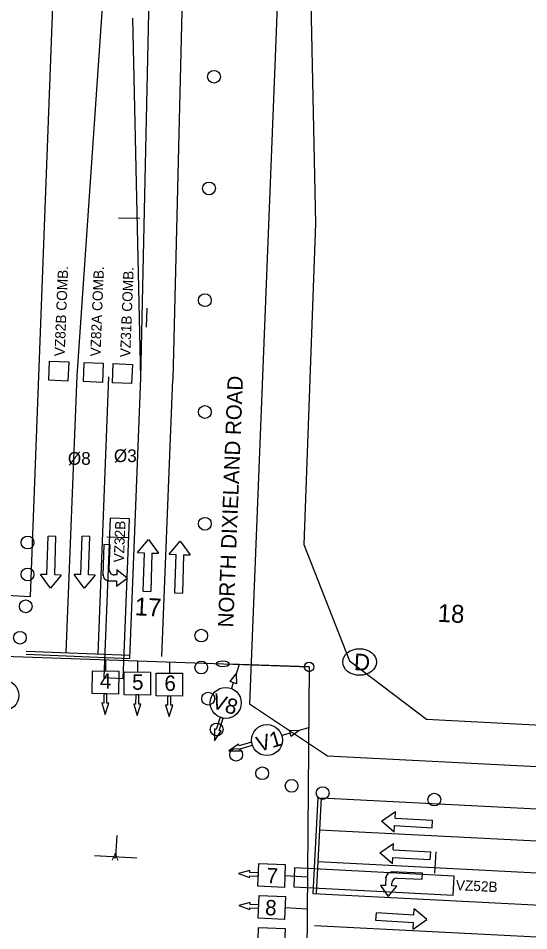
# Model space of a CAD drawing. Extents: x 0 to 1361828, y 0 to 1470398.
# Drawn here: x 680949.1 to 681108.9, y 735115.8 to 735401.5 of the extents above; entities that cross this region are included whole.
import ezdxf

# ---------------------------------------------------------------- set-up
doc = ezdxf.new("R2010")
doc.units = 0
for name, color, linetype in [('$', 7, 'Continuous'), ('090338 Base_Design base 1-1 - R_Horz Alg', 7, 'Continuous'), ('MOT Stage 1', 7, 'Continuous'), ('MOT Stage 1 Lanes', 7, 'Continuous'), ('R_Horz Alg Station', 7, 'Continuous'), ('RW-EX', 7, 'Continuous'), ('RW-PR', 7, 'Continuous'), ('SIGNAL-PLAN VIEW LABLES', 7, 'Continuous'), ('TITEXT', 7, 'Continuous'), ('Video-Zones-pr', 7, 'Continuous')]:
    doc.layers.add(name, color=color, linetype=linetype)

# ---------------------------------------------------------------- blocks, each defined once
blk = doc.blocks.new('BAREL_1503')
at = {"layer": 'MOT Stage 1'}
blk.add_circle((0, 0.01), 2.88, dxfattribs=at)
blk = doc.blocks.new('SARROW_170')
at = {"layer": 'MOT Stage 1'}
for p, q in [((0, 0), (-6, 0)), ((0, -29.42), (0, 0)), ((-6, -29.42), (-6, 0)), ((-6, -29.42), (-11, -29.42)), ((-3, -39.81), (-11, -29.42)), ((5, -29.42), (-3, -39.81)), ((5, -29.42), (0, -29.42))]:
    blk.add_line(p, q, dxfattribs=at)
blk = doc.blocks.new('SARROW_171')
at = {"layer": 'MOT Stage 1'}
for p, q in [((-6, -29.42), (-6, 0)), ((0, 0), (-6, 0)), ((0, -29.42), (0, 0)), ((-6, -29.42), (-11, -29.42)), ((-3, -39.81), (-11, -29.42)), ((5, -29.42), (-3, -39.81)), ((5, -29.42), (0, -29.42))]:
    blk.add_line(p, q, dxfattribs=at)
blk = doc.blocks.new('SARROW_173')
at = {"layer": 'MOT Stage 1'}
for p, q in [((0, 0), (-6, 0)), ((0, -29.42), (0, 0)), ((-6, -29.42), (-6, 0)), ((-6, -29.42), (-11, -29.42)), ((-3, -39.81), (-11, -29.42)), ((5, -29.42), (-3, -39.81)), ((5, -29.42), (0, -29.42))]:
    blk.add_line(p, q, dxfattribs=at)
blk = doc.blocks.new('SARROW_174')
at = {"layer": 'MOT Stage 1'}
for p, q in [((-6, -29.42), (-6, 0)), ((0, 0), (-6, 0)), ((0, -29.42), (0, 0)), ((-6, -29.42), (-11, -29.42)), ((-3, -39.81), (-11, -29.42)), ((5, -29.42), (-3, -39.81)), ((5, -29.42), (0, -29.42))]:
    blk.add_line(p, q, dxfattribs=at)
blk = doc.blocks.new('SARROW_175')
at = {"layer": 'MOT Stage 1'}
for p, q in [((-6, -29.42), (-6, 0)), ((0, 0), (-6, 0)), ((0, -29.42), (0, 0)), ((-6, -29.42), (-11, -29.42)), ((-3, -39.81), (-11, -29.42)), ((5, -29.42), (-3, -39.81)), ((5, -29.42), (0, -29.42))]:
    blk.add_line(p, q, dxfattribs=at)
blk = doc.blocks.new('BAREL_1543')
at = {"layer": 'MOT Stage 1'}
blk.add_circle((0, 0.01), 2.88, dxfattribs=at)
blk = doc.blocks.new('BAREL_1544')
at = {"layer": 'MOT Stage 1'}
blk.add_circle((0, 0.01), 2.88, dxfattribs=at)
blk = doc.blocks.new('BAREL_1545')
at = {"layer": 'MOT Stage 1'}
blk.add_circle((0, 0.01), 2.88, dxfattribs=at)
blk = doc.blocks.new('BAREL_1546')
at = {"layer": 'MOT Stage 1'}
blk.add_circle((0, 0.01), 2.88, dxfattribs=at)
blk = doc.blocks.new('BAREL_1547')
at = {"layer": 'MOT Stage 1'}
blk.add_circle((0, 0.01), 2.88, dxfattribs=at)
blk = doc.blocks.new('BAREL_1548')
at = {"layer": 'MOT Stage 1'}
blk.add_circle((0, 0.01), 2.88, dxfattribs=at)
blk = doc.blocks.new('BAREL_1549')
at = {"layer": 'MOT Stage 1'}
blk.add_circle((0, 0.01), 2.88, dxfattribs=at)
blk = doc.blocks.new('BAREL_1550')
at = {"layer": 'MOT Stage 1'}
blk.add_circle((0, 0.01), 2.88, dxfattribs=at)
blk = doc.blocks.new('BAREL_1551')
at = {"layer": 'MOT Stage 1'}
blk.add_circle((0, 0.01), 2.88, dxfattribs=at)
blk = doc.blocks.new('BAREL_1552')
at = {"layer": 'MOT Stage 1'}
blk.add_circle((0, 0.01), 2.88, dxfattribs=at)
blk = doc.blocks.new('BAREL_1553')
at = {"layer": 'MOT Stage 1'}
blk.add_circle((0, 0.01), 2.88, dxfattribs=at)
blk = doc.blocks.new('BAREL_1554')
at = {"layer": 'MOT Stage 1'}
blk.add_circle((0, 0.01), 2.88, dxfattribs=at)
blk = doc.blocks.new('BAREL_1555')
at = {"layer": 'MOT Stage 1'}
blk.add_circle((0, 0.01), 2.88, dxfattribs=at)
blk = doc.blocks.new('SARROW_180')
at = {"layer": 'MOT Stage 1'}
for p, q in [((-6, -29.42), (-6, 0)), ((0, 0), (-6, 0)), ((0, -29.42), (0, 0)), ((-6, -29.42), (-11, -29.42)), ((-3, -39.81), (-11, -29.42)), ((5, -29.42), (-3, -39.81)), ((5, -29.42), (0, -29.42))]:
    blk.add_line(p, q, dxfattribs=at)
blk = doc.blocks.new('SARROW_183')
at = {"layer": 'MOT Stage 1'}
for p, q in [((-6, -29.42), (-6, 0)), ((0, 0), (-6, 0)), ((0, -29.42), (0, 0)), ((-6, -29.42), (-11, -29.42)), ((-3, -39.81), (-11, -29.42)), ((5, -29.42), (-3, -39.81)), ((5, -29.42), (0, -29.42))]:
    blk.add_line(p, q, dxfattribs=at)
blk = doc.blocks.new('BAREL_1579')
at = {"layer": 'MOT Stage 1'}
blk.add_circle((0, 0.01), 2.88, dxfattribs=at)
blk = doc.blocks.new('BAREL_1580')
at = {"layer": 'MOT Stage 1'}
blk.add_circle((0, 0.01), 2.88, dxfattribs=at)
blk = doc.blocks.new('BAREL_1581')
at = {"layer": 'MOT Stage 1'}
blk.add_circle((0, 0.01), 2.88, dxfattribs=at)
blk = doc.blocks.new('BAREL_1582')
at = {"layer": 'MOT Stage 1'}
blk.add_circle((0, 0.01), 2.88, dxfattribs=at)

msp = doc.modelspace()

# ---------------------------------------------------------------- linework, layer by layer
at = {"layer": '$'}
msp.add_line((681040.12, 735198.43), (681015.14, 735199.31), dxfattribs=at)
msp.add_lwpolyline([(680910.95, 735083.16), (680920.66, 735202.66), (681040.12, 735198.43), (681039.25, 735082.83), (680910.95, 735083.16)], dxfattribs=at)
msp.add_circle((681040.12, 735198.43), 1.5, dxfattribs=at)
msp.add_ellipse((681013.12, 735199.39), major_axis=(-2.02, 0.07), ratio=0.447722, dxfattribs=at)
at = {"layer": 'MOT Stage 1'}
for points in [[(680975.9, 735236.75), (680975.59, 735227.05), (680975.6, 735227.37)], [(680977.55, 735228.89), (680977.8, 735236.69), (680975.9, 735236.75)], [(680977.44, 735225.4), (680977.12, 735225.41), (680979.85, 735225.33), (680979.8, 735223.74), (680983.18, 735226.17), (680979.97, 735228.82), (680979.92, 735227.23), (680979.09, 735227.26)], [(681075.58, 735133.87), (681065.81, 735134.24), (681066.13, 735134.22)], [(681067.66, 735132.25), (681075.51, 735131.95), (681075.58, 735133.87)], [(681064.14, 735132.38), (681064.15, 735132.7), (681064.05, 735129.95), (681062.45, 735130.01), (681064.89, 735126.59), (681067.57, 735129.81), (681065.97, 735129.87), (681066, 735130.71)]]:
    msp.add_lwpolyline(points, dxfattribs=at)
for centre, radius, start, end in [((680979.14, 735228.84), 1.59, 178.1773, 268.1773), ((680977.5, 735227.31), 1.9, 178.1773, 268.1773), ((681066.06, 735132.31), 1.92, 87.8614, 177.8614), ((681067.6, 735130.65), 1.6, 87.8614, 177.8614)]:
    msp.add_arc(centre, radius, start, end, dxfattribs=at)
at = {"layer": 'MOT Stage 1 Lanes'}
for p, q in [((680967.48, 735289.6), (680982.89, 735514.32)), ((680987.46, 735288.81), (680992.34, 735513.78)), ((681002.99, 735513.22), (680997.45, 735288.41)), ((680987.46, 735288.81), (680984.91, 735401.49)), ((680964.06, 735202.89), (680967.48, 735289.6)), ((680974.05, 735202.5), (680977.47, 735289.2)), ((680994.03, 735201.71), (680997.45, 735288.41)), ((681043.86, 735157.43), (681230.33, 735147.83)), ((681043.34, 735147.44), (681229.82, 735137.84)), ((681042.83, 735137.46), (681229.3, 735127.86)), ((681041.8, 735117.48), (681228.28, 735107.88))]:
    msp.add_line(p, q, dxfattribs=at)
for points in [[(680951.55, 735202.38), (680984, 735201.1), (680987.46, 735288.81)], [(680951.59, 735203.38), (680984.04, 735202.1)], [(681042.86, 735157.48), (681041.31, 735127.52), (681228.79, 735117.87)], [(681043.86, 735157.43), (681042.31, 735127.47)]]:
    msp.add_lwpolyline(points, dxfattribs=at)
at = {"layer": 'R_Horz Alg Station'}
for points in [[(680980.48, 735339.05), (680987.14, 735338.86)], [(680976.83, 735239.19), (680983.49, 735238.92)], [(680979.89, 735145.66), (680979.55, 735139)], [(680972.89, 735139.34), (680986.21, 735138.66)], [(681079.76, 735140.5), (681079.41, 735133.84)]]:
    msp.add_lwpolyline(points, dxfattribs=at)
at = {"layer": 'RW-EX'}
for p, q in [((680952.9, 735220.48), (680961.67, 735453.52)), ((681031.32, 735436.64), (681029.35, 735386.67)), ((681029.35, 735386.67), (681021.47, 735186.9)), ((680943.65, 735220.95), (680952.9, 735220.48)), ((681021.47, 735186.9), (681045.84, 735170.62)), ((681045.84, 735170.62), (681414.69, 735151.56))]:
    msp.add_line(p, q, dxfattribs=at)
at = {"layer": 'RW-PR'}
for points in [[(681033.2, 735487.55), (681040.06, 735436.31), (681042.12, 735337.22)], [(681042.12, 735337.22), (681038.45, 735236.76), (681052.81, 735200.3)], [(681052.81, 735200.3), (681076.9, 735182.04), (681126.83, 735179.45), (681173.16, 735184.07)]]:
    msp.add_lwpolyline(points, dxfattribs=at)
at = {"layer": 'SIGNAL-PLAN VIEW LABLES'}
for p, q in [((680975.84, 735190.01), (680975.82, 735187.12)), ((680976.85, 735189.99), (680975.84, 735190.01)), ((680976.83, 735187.11), (680976.85, 735189.99)), ((680985.84, 735189.65), (680985.82, 735186.77)), ((680986.85, 735189.64), (680985.84, 735189.65)), ((680986.83, 735186.76), (680986.85, 735189.64)), ((680995.84, 735189.3), (680995.82, 735186.41)), ((680996.84, 735189.28), (680995.84, 735189.3)), ((680996.82, 735186.41), (680996.84, 735189.28)), ((680975.82, 735187.12), (680975.22, 735187.13)), ((680975.22, 735187.13), (680976.3, 735183.58)), ((680976.3, 735183.58), (680977.43, 735187.11)), ((680977.43, 735187.11), (680976.83, 735187.11)), ((680985.82, 735186.77), (680985.21, 735186.77)), ((680985.21, 735186.77), (680986.3, 735183.23)), ((680986.3, 735183.23), (680987.43, 735186.76)), ((680987.43, 735186.76), (680986.83, 735186.76)), ((680995.82, 735186.41), (680995.21, 735186.42)), ((680995.21, 735186.42), (680996.3, 735182.87)), ((680996.3, 735182.87), (680997.43, 735186.4)), ((680997.43, 735186.4), (680996.82, 735186.41)), ((681021.61, 735134.68), (681018.02, 735133.75)), ((681018.02, 735133.75), (681021.49, 735132.47)), ((681021.58, 735134.08), (681021.61, 735134.68)), ((681024.27, 735133.94), (681021.58, 735134.08)), ((681024.23, 735132.93), (681024.27, 735133.94)), ((681021.49, 735132.47), (681021.53, 735133.07)), ((681021.53, 735133.07), (681024.23, 735132.93)), ((681021.68, 735124.66), (681018.09, 735123.74)), ((681018.09, 735123.74), (681021.57, 735122.45)), ((681021.57, 735122.45), (681021.6, 735123.05)), ((681021.6, 735123.05), (681024.31, 735122.91)), ((681021.65, 735124.06), (681021.68, 735124.66)), ((681024.35, 735123.92), (681021.65, 735124.06)), ((681024.31, 735122.91), (681024.35, 735123.92))]:
    msp.add_line(p, q, dxfattribs=at)
for points in [[(680976.42, 735200.68), (680976.39, 735197.17)], [(680986.41, 735200.33), (680986.39, 735196.82)], [(680996.41, 735199.98), (680996.39, 735196.46)], [(681018.23, 735199.2), (681017.3, 735196.31)], [(681016.38, 735193.5), (681015.79, 735191.67)], [(680975.84, 735190.01), (680975.82, 735187.12), (680975.22, 735187.13), (680976.3, 735183.58), (680977.43, 735187.11), (680976.83, 735187.11), (680976.85, 735189.99)], [(680985.84, 735189.65), (680985.82, 735186.77), (680985.21, 735186.77), (680986.3, 735183.23), (680987.43, 735186.76), (680986.83, 735186.76), (680986.85, 735189.64)], [(680995.84, 735189.3), (680995.82, 735186.41), (680995.21, 735186.42), (680996.3, 735182.87), (680997.43, 735186.4), (680996.82, 735186.41), (680996.84, 735189.28)], [(681011.05, 735178.86), (681010.48, 735179.04), (681010.47, 735175.33), (681012.59, 735178.38), (681012.01, 735178.56), (681013.23, 735182.4), (681012.27, 735182.71), (681011.05, 735178.86)], [(681012.27, 735182.71), (681011.05, 735178.86), (681010.48, 735179.04), (681010.47, 735175.33), (681012.59, 735178.38), (681012.01, 735178.56), (681013.23, 735182.4)], [(681039.98, 735179.33), (681037.06, 735178.48)], [(681034.22, 735177.66), (681031.58, 735176.91)], [(681018.2, 735173.7), (681018.02, 735174.27), (681014.97, 735172.15), (681018.68, 735172.16), (681018.5, 735172.74), (681022.35, 735173.95), (681022.04, 735174.91), (681018.2, 735173.7)], [(681022.04, 735174.91), (681018.2, 735173.7), (681018.02, 735174.27), (681014.97, 735172.15), (681018.68, 735172.16), (681018.5, 735172.74), (681022.35, 735173.95)], [(681024.27, 735133.94), (681021.58, 735134.08), (681021.61, 735134.68), (681018.02, 735133.75), (681021.49, 735132.47), (681021.53, 735133.07), (681024.23, 735132.93)], [(681039.63, 735132.61), (681032.5, 735132.98)], [(681024.35, 735123.92), (681021.65, 735124.06), (681021.68, 735124.66), (681018.09, 735123.74), (681021.57, 735122.45), (681021.6, 735123.05), (681024.31, 735122.91)], [(681039.55, 735122.61), (681032.58, 735122.96)]]:
    msp.add_lwpolyline(points, dxfattribs=at)
for points in [[(680972.21, 735190.06), (680972.26, 735197.2), (680980.52, 735197.14), (680980.47, 735189.94)], [(680982.21, 735189.71), (680982.26, 735196.84), (680990.52, 735196.79), (680990.47, 735189.58)], [(680992.21, 735189.35), (680992.26, 735196.49), (681000.52, 735196.43), (681000.47, 735189.23)], [(681017.3, 735196.31), (681017.37, 735193.17), (681015.4, 735193.83)], [(681037.06, 735178.48), (681034.5, 735176.65), (681033.94, 735178.66)], [(681024.12, 735129.74), (681024.37, 735136.87), (681032.63, 735136.58), (681032.38, 735129.38)], [(681024.2, 735119.72), (681024.45, 735126.85), (681032.7, 735126.56), (681032.45, 735119.36)], [(681024.08, 735109.71), (681024.33, 735116.84), (681032.58, 735116.56), (681032.33, 735109.36)]]:
    msp.add_lwpolyline(points, close=True, dxfattribs=at)
for centre in [(680944.37, 735189.5), (681014.02, 735187.16), (681026.93, 735175.52)]:
    msp.add_circle(centre, 4.85, dxfattribs=at)
msp.add_ellipse((681055.92, 735199.96), major_axis=(-5.27, 0), ratio=0.790685, dxfattribs=at)
at = {"layer": 'Video-Zones-pr'}
for points in [[(680989.17, 735304.75), (680989.4, 735310.75)], [(680958.87, 735294.17), (680964.87, 735293.93), (680964.63, 735287.93), (680958.64, 735288.17)], [(680958.64, 735288.17), (680958.87, 735294.17)], [(680969.7, 735293.74), (680975.7, 735293.5), (680975.46, 735287.51), (680969.47, 735287.74)], [(680969.47, 735287.74), (680969.7, 735293.74)], [(680978.81, 735293.38), (680984.8, 735293.14), (680984.57, 735287.15), (680978.57, 735287.38)], [(680978.57, 735287.38), (680978.81, 735293.38)]]:
    msp.add_lwpolyline(points, dxfattribs=at)
for points in [[(680977.85, 735245.02), (680975.88, 735195.06), (680981.88, 735194.83), (680983.85, 735244.79)], [(681035.29, 735129.56), (681085.23, 735126.98), (681085.54, 735132.97), (681035.6, 735135.55)]]:
    msp.add_lwpolyline(points, close=True, dxfattribs=at)

# ---------------------------------------------------------------- block references
at = {"layer": 'MOT Stage 1'}
for name, p, xscale, yscale, rotation in [('BAREL_1555', (681010.36, 735383.17), 0.6945420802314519, 0.6945420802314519, 87.04179557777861), ('BAREL_1554', (681008.8, 735348.2), 0.6945420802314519, 0.6945420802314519, 87.04179557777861), ('BAREL_1553', (681007.5, 735313.23), 0.6945420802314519, 0.6945420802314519, 87.04179557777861), ('BAREL_1552', (681007.5, 735278.23), 0.6945420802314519, 0.6945420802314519, 87.04179557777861), ('BAREL_1551', (681007.5, 735243.23), 0.6945420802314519, 0.6945420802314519, 87.04179557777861), ('BAREL_1582', (680951.98, 735237.37), 0.6945420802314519, 0.6945420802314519, 83.20696384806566), ('SARROW_170', (680960.87, 735239.23), 0.4075873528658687, 0.4075873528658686, -1.8227149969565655), ('SARROW_180', (680971.47, 735239.23), 0.4075873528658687, 0.4075873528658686, -1.8227149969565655), ('SARROW_171', (680988.1, 735222.16), 0.4075873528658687, 0.4075873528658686, 178.17728500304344), ('SARROW_183', (680998, 735221.63), 0.4075873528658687, 0.4075873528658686, 178.17728500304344), ('BAREL_1581', (680951.98, 735227.37), 0.6945420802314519, 0.6945420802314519, 83.20696384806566), ('BAREL_1580', (680951.42, 735217.38), 0.6945420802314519, 0.6945420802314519, 83.20696384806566), ('BAREL_1579', (680949.59, 735207.55), 0.6945420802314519, 0.6945420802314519, 83.20696384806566), ('BAREL_1550', (681006.36, 735208.24), 0.6945420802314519, 0.6945420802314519, 87.04179557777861), ('BAREL_1549', (681006.36, 735198.24), 0.6945420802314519, 0.6945420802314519, 87.04179557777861), ('BAREL_1548', (681008.53, 735188.48), 0.6945420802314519, 0.6945420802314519, 87.04179557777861), ('BAREL_1547', (681011.18, 735178.84), 0.6945420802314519, 0.6945420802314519, 87.04179557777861), ('BAREL_1546', (681017.29, 735170.93), 0.6945420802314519, 0.6945420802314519, 87.04179557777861), ('BAREL_1545', (681025.45, 735165.14), 0.6945420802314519, 0.6945420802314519, 87.04179557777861), ('BAREL_1544', (681034.64, 735161.2), 0.6945420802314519, 0.6945420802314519, 87.04179557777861), ('BAREL_1543', (681044.38, 735158.93), 0.6945420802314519, 0.6945420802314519, 87.04179557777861), ('BAREL_1503', (681079.32, 735156.89), 0.6945420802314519, 0.6945420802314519, 87.04179557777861), ('SARROW_174', (681078.63, 735148.07), 0.39999999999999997, 0.39999999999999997, -93.21769625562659), ('SARROW_175', (681078.07, 735138.09), 0.39999999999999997, 0.39999999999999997, -93.21769625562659), ('SARROW_173', (681061.06, 735119), 0.40000000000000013, -0.40000000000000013, -93.21769625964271)]:
    msp.add_blockref(name, p, dxfattribs=dict(at, xscale=xscale, yscale=yscale, rotation=rotation))

# ---------------------------------------------------------------- texts
at = {"layer": '$'}
for s, height, rotation, p in [('VZ82B COMB.', 3.2, 87.7397, (680963.59, 735295.62)), ('VZ82A COMB.', 3.2, 87.7397, (680974.79, 735295.54)), ('VZ31B COMB.', 3.2, 87.7397, (680984.11, 735295.3)), ('NORTH DIXIELAND ROAD', 4.8, 87.7567, (681016.36, 735210.72)), ('VZ32B', 3.2, 87.7397, (680982.13, 735231.07)), ('17', 5.6, 357.065, (680985.41, 735214.6)), ('18', 5.6, 357.0415, (681080.28, 735212.57)), ('VZ52B', 3.2, 357.065, (681085.99, 735128.58))]:
    msp.add_text(s, height=height, rotation=rotation, dxfattribs=at).set_placement(p)
at = {"layer": '090338 Base_Design base 1-1 - R_Horz Alg'}
msp.add_text('A', height=2.4, rotation=357.0533, dxfattribs=at).set_placement((680978.3, 735137.87))
at = {"layer": 'SIGNAL-PLAN VIEW LABLES'}
for s, height, rotation, p in [('D', 5.2, 357.0414, (681054.06, 735197.45)), ('4', 4.8, 359.5982, (680974.58, 735191.64)), ('5', 4.8, 359.5982, (680984.69, 735191.29)), ('6', 4.8, 359.5982, (680994.81, 735190.94)), ('V8', 4.8, 342.4643, (681009.34, 735185.69)), ('V1', 4.8, 16.5013, (681024.45, 735171.78)), ('7', 4.8, 357.0414, (681026.71, 735130.76)), ('8', 4.8, 357.0414, (681026.26, 735120.75))]:
    msp.add_text(s, height=height, rotation=rotation, dxfattribs=at).set_placement(p)
at = {"layer": 'TITEXT'}
for s, p in [('%%C8', (680964.61, 735261.69)), ('%%C3', (680979.02, 735262.54))]:
    msp.add_text(s, height=4, dxfattribs=at).set_placement(p)

doc.saveas('drawing.dxf')
